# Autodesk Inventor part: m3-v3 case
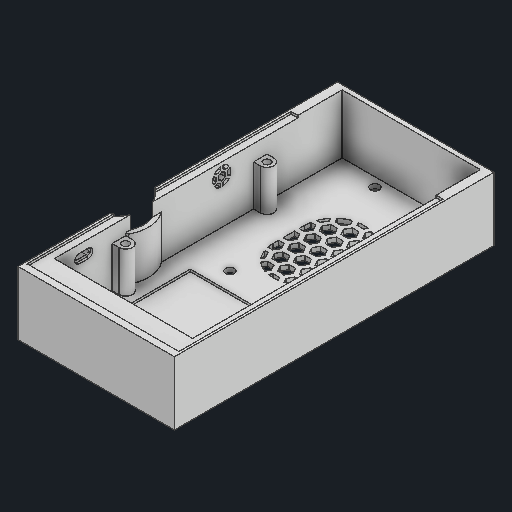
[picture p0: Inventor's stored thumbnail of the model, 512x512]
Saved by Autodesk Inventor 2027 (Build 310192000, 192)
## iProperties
Created: 2026-10
Part Number: m3-v3 case
Material: 일반
Document SubType Name: Modeling
Designer: khw
Density: 1 g/cm^3
Appearance: 기본값
Author: khw
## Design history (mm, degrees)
sketch "스케치1"
  geometry: L1 (0, 0)-(61, 0); L2 (61, 0)-(61, -106); L3 (61, -106)-(0, -106); L4 (0, -106)-(0, 0); L5 (64, 9)-(-3, 9); L6 (-3, 9)-(-3, -107.5); L7 (-3, -107.5)-(64, -107.5); L8 (64, -107.5)-(64, 9); L9 (49, -10)-(35, -10); L10 (35, -10)-(35, -17); L11 (35, -17)-(49, -17); L12 (49, -17)-(49, -10); L13 (58, -28.5)-(3, -28.5); L14 (3, -28.5)-(3, -90.9); L15 (3, -90.9)-(58, -90.9); L16 (58, -90.9)-(58, -28.5); L17 (52, -25)-(9, -25); L18 (9, -25)-(9, -51); L19 (9, -51)-(52, -51); L20 (52, -51)-(52, -25); L21 (18.5, -59)-(42.5, -59); L22 (30.5, -65)-(30.5, -79); L23 (35.119, -80)-(38.006, -80); L24 (31.943, -81.5)-(29.057, -81.5); L25 (33.387, -79)-(31.943, -81.5); L26 (29.057, -81.5)-(27.613, -79); L27 (42.5, -113)-(42.5, -49); L28 (18.5, -113)-(18.5, -49); L29 (18.5, -49)-(18.5, -113); L30 (42.5, -59)-(42.5, -123); L31 (18.5, -123)-(18.5, -59); L32 (18.5, -59)-(18.5, -123); L33 (42.5, -123)-(18.5, -123); L34 (33.675, -82.5)-(35.119, -80); L35 (22.994, -71)-(25.881, -71); L36 (27.613, -72)-(29.057, -69.5); L37 (29.057, -74.5)-(27.613, -72); L38 (31.943, -69.5)-(33.387, -72); L39 (29.057, -76.5)-(31.943, -76.5); L40 (39.449, -68.5)-(38.006, -71); L41 (31.943, -76.5)-(33.387, -79); L42 (29.057, -69.5)-(31.943, -69.5); L43 (25.881, -71)-(27.325, -68.5); L44 (35.119, -71)-(33.675, -68.5); L45 (38.006, -71)-(35.119, -71); L46 (38.006, -80)-(39.449, -82.5); L47 (39.449, -82.5)-(38.006, -85); L48 (38.006, -85)-(35.119, -85); L49 (30.5, -79)-(30.5, -93); L50 (30.5, -86)-(17.5, -86); L51 (25.881, -87)-(27.325, -89.5); L52 (25.881, -92)-(22.994, -92); L53 (22.994, -87)-(25.881, -87); L54 (21.551, -89.5)-(22.994, -87); L55 (22.994, -92)-(21.551, -89.5); L56 (17.5, -93)-(17.5, -79); L57 (17.5, -79)-(17.5, -93); L58 (27.613, -86)-(29.057, -88.5); L59 (30.5, -93)-(30.5, -79); L60 (31.943, -90.5)-(29.057, -90.5); L61 (29.057, -88.5)-(31.943, -88.5); L62 (29.057, -67.5)-(27.613, -65); L63 (35.119, -66)-(38.006, -66); L64 (39.738, -79)-(41.181, -76.5)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; C1 r 1.6 at (58, -28.5); C2 r 1.6 at (3, -28.5); C3 r 1.6 at (3, -90.9); C4 r 1.6 at (58, -90.9); C5 r 2 at (42.5, -59); C6 r 2 at (18.5, -59); C7 r 2 at (18.5, -123); C8 r 2 at (42.5, -123); A1 r 3 centre (58, -28.5) between (58, -25.5) and (58, -31.5); A2 r 3 centre (3, -28.5) between (3, -31.5) and (3, -25.5); A3 r 3 centre (3, -90.9) between (3, -93.9) and (3, -87.9); A4 r 3 centre (58, -90.9) between (58, -93.9) and (58, -87.9); A5 r 13 centre (30.5, -79) between (43.5, -79) and (17.5, -79); A6 r 13 centre (30.5, -79) between (43.5, -79) and (17.5, -79); A7 r 13 centre (30.5, -93) between (17.5, -93) and (43.5, -93); A8 r 13 centre (30.5, -93) between (17.5, -93) and (43.5, -93); A9 r 13 centre (30.5, -93) between (17.5, -93) and (43.5, -93); A10 r 12.5 centre (72.5, -38.5) between (65, -28.5) and (65, -48.5); A11 r 14.5 centre (72.5, -38.5) between (59.802, -31.5) and (65, -50.91); 91 further points; 1 other entity
  constraints: 492 end point, 151 symmetric about line, 26 point on circle, 20 parallel, 19 centre point, 19 coincident, 17 midpoint, 14 perpendicular, 11 horizontal, 10 point on line, 9 tangent, 6 vertical alignment, 4 vertical, 3 equal length, 1 concentric, 1 line through centre, 147 other
  dimensions: "d0" = 61 distance of L2.end L3.end; "d1" = 106 distance of L1.end L2.end; "d2" = 9 distance between parallel lines of L1 L5; "d3" = 1.5 distance between parallel lines of L7 L3; "d4" = 3 distance between parallel lines of L2 L8; "d6" = 13.5 distance from line of L1 point (49, -13.5); "d8" = 7 distance of L11.end L9.start; "d9" = 14 distance of L10.end L11.end; "d11" = 62.4 distance of L15.end L13.start; "d12" = 55 distance of L13.start L13.end; "d13" = 3.2 diameter of C1; "d14" = 6 diameter of A1; "d15" = 3.2 diameter of C2; "d16" = 6 diameter of A2; "d17" = 3.2 diameter of C3; "d18" = 6 diameter of A3; "d19" = 3.2 diameter of C4; "d20" = 6 diameter of A4; "d22" = 26 distance of L17.end L18.end; "d23" = 43 distance of L18.end L19.end; "d24" = 22 distance from line of L8 point (42, -17); "d33" = 24 distance of L21.start L21.end; "d34" = 64 distance of L31.start L21.start; "d35" = 4 diameter of C5; "d36" = 4 diameter of C6; "d37" = 4 diameter of C8; "d38" = 4 diameter of C7; "d39" = 27 distance from line of L21 point (30.5, -86); "d40" = 40 distance of point (30.5, -106) point (30.5, -66); "d41" = 26 distance between parallel lines of L80 L72; "d42" = 2 distance between parallel lines of L24 L201; "d43" = 2 distance from line of point (32.665, -84.75) L204; "d44" = 2 distance between parallel lines of L25 L34; "d45" = 7 distance of L49.start L180.start; "d46" = 2 distance between parallel lines of L46 L73; "d47" = 2 distance from line of point (38.727, -76.75) L64; "d48" = 7 distance of L73.start L65.start; "d51" = 8 distance from line of point (30.5, -51) L21; "d52" = 8 distance between parallel lines of L11 L17; "d53" = 3 distance between parallel lines of L225 L5; "d54" = 6 distance from line of L227 point (30.5, -123); "d55" = 1 distance between parallel lines of L226 L6; "d56" = 10 distance from line of A1.centre L228; "d57" = 20 distance of A10.end A10.start; "d58" = 1 distance from line of L228.start L2; "d59" = 2 distance between parallel lines of L227 L231; "d70" = 2 radial gap between concentric circles of A11 A10; "d77" = 28.5 distance between parallel lines of L1 L13
  node "스케치 - 직사각형 패턴1" dims "d45" = 7, "d49" = 10
  node "스케치 - 직사각형 패턴2" dims "d48" = 7, "d50" = 10
extrude "돌출1" new body sketch "스케치1" distance "d60" = 2; taper "d61" = 0 deg
extrude "돌출2" join sketch "스케치1" distance "d62" = 26; taper "d63" = 0 deg
extrude "돌출3" cut sketch "스케치1" distance "d64" = 1; taper "d65" = 0 deg
extrude "돌출4" join sketch "스케치1" distance "d66" = 18; taper "d67" = 0 deg; dims "d68" = 2, "d69" = 0
extrude "돌출5" join sketch "스케치1" distance "d71" = 19.2; taper "d72" = 0 deg
sketch "스케치2"
  geometry: L1 (-39.449, 75.5)-(-38.006, 78) reference; L2 (-39.738, 86)-(-41.181, 88.5) reference; L3 (-41.181, 88.5)-(-39.738, 86) reference; L4 (-29.057, 88.5)-(-31.943, 88.5) reference; L5 (-31.943, 88.5)-(-29.057, 88.5) reference; L6 (-35.119, 92)-(-38.006, 92) reference; L7 (-44.068, 88.5)-(-41.181, 88.5) reference; L8 (-41.181, 88.5)-(-44.068, 88.5) reference; L9 (-45.511, 86)-(-44.068, 88.5) reference; L10 (-44.068, 88.5)-(-45.511, 86) reference; L11 (-44.068, 83.5)-(-45.511, 86) reference; L12 (-22.994, 92)-(-21.551, 89.5) reference; L13 (-15.489, 79)-(-16.932, 81.5) reference; L14 (-15.489, 86)-(-16.932, 88.5) reference; L15 (-16.932, 88.5)-(-15.489, 86) reference; L16 (-22.994, 80)-(-21.551, 82.5) reference; L17 (-19.819, 81.5)-(-21.262, 79) reference; L18 (-25.881, 80)-(-22.994, 80) reference; L19 (-21.551, 82.5)-(-22.994, 85) reference; L20 (-22.994, 78)-(-25.881, 78) reference; L21 (-16.932, 81.5)-(-19.819, 81.5) reference; L22 (-21.262, 79)-(-19.819, 76.5) reference; L23 (-19.819, 76.5)-(-16.932, 76.5) reference; L24 (-16.932, 76.5)-(-15.489, 79) reference; L25 (-22.994, 85)-(-25.881, 85) reference; L26 (-27.325, 89.5)-(-25.881, 92) reference; L27 (-43.5, 79)-(-43.5, 93) reference; L28 (-19.819, 90.5)-(-21.262, 93) reference; L29 (-16.932, 88.5)-(-19.819, 88.5) reference; L30 (-19.819, 88.5)-(-16.932, 88.5) reference; L31 (-16.932, 83.5)-(-15.489, 86) reference; L32 (-19.819, 83.5)-(-16.932, 83.5) reference; L33 (-16.932, 102.5)-(-15.489, 100) reference; L34 (-35.119, 99)-(-38.006, 99) reference; L35 (-33.675, 96.5)-(-35.119, 99) reference; L36 (-35.119, 101)-(-33.675, 103.5) reference; L37 (-39.449, 103.5)-(-38.006, 101) reference; L38 (-38.006, 106)-(-39.449, 103.5) reference; L39 (-33.387, 107)-(-31.943, 104.5) reference; L40 (-25.881, 78)-(-27.325, 75.5) reference; L41 (-35.119, 78)-(-33.675, 75.5) reference; L42 (-38.006, 78)-(-35.119, 78) reference; L43 (-27.613, 79)-(-29.057, 76.5) reference; L44 (-44.068, 76.5)-(-45.511, 79) reference; L45 (-41.181, 76.5)-(-44.068, 76.5) reference; L46 (-35.119, 73)-(-38.006, 73) reference; L47 (-27.325, 75.5)-(-25.881, 73) reference; L48 (-39.738, 93)-(-41.181, 95.5) reference; L49 (-41.181, 97.5)-(-39.738, 100) reference; L50 (-44.068, 95.5)-(-45.511, 93) reference; L51 (-41.181, 95.5)-(-44.068, 95.5) reference; L52 (-39.738, 100)-(-41.181, 102.5) reference; L53 (-44.068, 97.5)-(-41.181, 97.5) reference; L54 (-41.181, 102.5)-(-44.068, 102.5) reference; L55 (-45.511, 100)-(-44.068, 97.5) reference; L56 (-44.068, 102.5)-(-45.511, 100) reference; L57 (-33.387, 100)-(-31.943, 97.5) reference; L58 (-31.943, 97.5)-(-29.057, 97.5) reference; L59 (-35.119, 94)-(-33.675, 96.5) reference; L60 (-31.943, 95.5)-(-33.387, 93) reference; L61 (-29.057, 95.5)-(-31.943, 95.5) reference; L62 (-38.006, 101)-(-35.119, 101) reference; L63 (-29.057, 102.5)-(-31.943, 102.5) reference; L64 (-35.119, 106)-(-38.006, 106) reference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; C1 r 2 at (-18.5, 123) reference; C2 r 1.6 at (-58, 90.9) reference; C3 r 2 at (-18.5, 59) reference; C4 r 2 at (-42.5, 59) reference; C5 r 1.6 at (-3, 90.9) reference; C6 r 2 at (-42.5, 123) reference; C7 r 1.6 at (-3, 28.5) reference; C8 r 1.6 at (-58, 28.5) reference; A1 r 13 centre (-30.5, 93) between (-17.5, 93) and (-43.5, 93) reference; A2 r 13 centre (-30.5, 93) between (-17.5, 93) and (-43.5, 93) reference; A3 r 13 centre (-30.5, 93) between (-17.5, 93) and (-43.5, 93) reference; A4 r 3 centre (-58, 90.9) between (-58, 87.9) and (-58, 93.9) reference; A5 r 13 centre (-30.5, 79) between (-43.5, 79) and (-17.5, 79) reference; A6 r 13 centre (-30.5, 79) between (-43.5, 79) and (-17.5, 79) reference; A7 r 12.5 centre (-72.5, 38.5) between (-65, 28.5) and (-65, 48.5) reference; A8 r 14.5 centre (-72.5, 38.5) between (-59.802, 31.5) and (-65, 50.91) reference; 85 further points; 3 other entities
  constraints: 3 vertical alignment, 7 other
extrude "돌출6" cut sketch "스케치2" distance "d73" = 1; taper "d74" = 0 deg
sketch "스케치3"
  geometry: L1 (98.9, 20)-(102.1, 20) reference; L2 (36.5, 20)-(39.7, 20) reference; L3 (55.1, 23.232)-(56.6, 22.366); L4 (56.6, 22.366)-(56.6, 20.634); L5 (56.6, 20.634)-(55.1, 19.768); L6 (55.1, 19.768)-(53.6, 20.634); L7 (53.6, 20.634)-(53.6, 22.366); L8 (53.6, 22.366)-(55.1, 23.232); L9 (59.1, 23.232)-(60.6, 22.366); L10 (60.6, 22.366)-(60.6, 20.634); L11 (60.6, 20.634)-(59.1, 19.768); L12 (59.1, 19.768)-(57.6, 20.634); L13 (57.6, 20.634)-(57.6, 22.366); L14 (57.6, 22.366)-(59.1, 23.232); L15 (55.1, 17.5)-(55.1, 25.5); L16 (55.6, 25.83)-(57.1, 26.696); L17 (57.1, 26.696)-(58.6, 25.83); L18 (58.6, 25.83)-(58.6, 24.098); L19 (57.1, 23.232)-(55.6, 24.098); L20 (58.6, 24.098)-(57.1, 23.232); L21 (55.6, 24.098)-(55.6, 25.83); L22 (51.6, 24.098)-(51.6, 25.83); L23 (51.6, 25.83)-(53.1, 26.696); L24 (53.1, 26.696)-(54.6, 25.83); L25 (54.6, 24.098)-(53.1, 23.232); L26 (54.6, 25.83)-(54.6, 24.098); L27 (53.1, 23.232)-(51.6, 24.098); L28 (51.1, 19.768)-(49.6, 20.634); L29 (49.6, 20.634)-(49.6, 22.366); L30 (49.6, 22.366)-(51.1, 23.232); L31 (52.6, 22.366)-(52.6, 20.634); L32 (51.1, 23.232)-(52.6, 22.366); L33 (52.6, 20.634)-(51.1, 19.768); L34 (54.6, 17.17)-(53.1, 16.304); L35 (53.1, 16.304)-(51.6, 17.17); L36 (51.6, 17.17)-(51.6, 18.902); L37 (53.1, 19.768)-(54.6, 18.902); L38 (51.6, 18.902)-(53.1, 19.768); L39 (54.6, 18.902)-(54.6, 17.17); L40 (58.6, 18.902)-(58.6, 17.17); L41 (58.6, 17.17)-(57.1, 16.304); L42 (57.1, 16.304)-(55.6, 17.17); L43 (55.6, 18.902)-(57.1, 19.768); L44 (55.6, 17.17)-(55.6, 18.902); L45 (57.1, 19.768)-(58.6, 18.902); L46 (114, 21.5)-(118, 21.5); L47 (114, 20.5)-(118, 20.5); L48 (118, 22.5)-(114, 22.5); C1 r 1 at (116, 21.5); A1 r 4 centre (55.1, 21.5) between (59.1, 21.5) and (55.1, 17.5); A2 r 1 centre (114, 21.5) between (114, 22.5) and (114, 20.5); A3 r 1 centre (118, 21.5) between (118, 20.5) and (118, 22.5); 19 further points
  constraints: 94 end point, 9 point on circle, 5 tangent, 4 centre point, 4 midpoint, 2 coincident, 2 horizontal alignment, 2 parallel, 1 horizontal, 1 vertical, 99 other
  dimensions: "d75" = 1.5 distance from line of L1 C1.centre; "d76" = 15.5 horizontal distance of C1.centre point (100.5, 20); "d78" = 8 diameter of A1; "d79" = 2 diameter of C1; "d80" = 17 horizontal distance of A1.centre point (38.1, 20); "d81" = 8 distance of L15.start L15.end; "d82" = 1 distance between parallel lines of L13 L4; "d85" = 360 deg dimension on A1.centre L9.start (derived); "d87" = 6 distance of point (119, 21.5) point (113, 21.5)
extrude "돌출7" cut sketch "스케치3" stored distance "d88" = 8 (derived); taper "d89" = 0 deg
sketch "스케치4"
  geometry: L1 (-10.5, 20.5)-(-14.5, 20.5) reference; L2 (-14.5, 18.5)-(-10.5, 18.5) reference; L3 (3, 26)-(3, -2) reference; L4 (-37.5, -2)-(3, -2) reference; L5 (-37.5, -2)-(-37.5, 26) reference; L6 (3, 26)-(-37.5, 26) reference; L7 (-10.5, 19.5)-(-14.5, 19.5); L8 (-10.5, 21.5)-(-14.5, 21.5); L9 (-14.5, 17.5)-(-10.5, 17.5); A1 r 1 centre (-10.5, 19.5) between (-10.5, 18.5) and (-10.5, 20.5) reference; A2 r 1 centre (-14.5, 19.5) between (-14.5, 20.5) and (-14.5, 18.5) reference; A3 r 2 centre (-10.5, 19.5) between (-10.5, 17.5) and (-10.5, 21.5); A4 r 2 centre (-14.5, 19.5) between (-14.5, 21.5) and (-14.5, 17.5); 2 further points
  constraints: 8 end point, 4 point on circle, 4 tangent, 2 centre point, 1 horizontal, 1 midpoint, 1 parallel
  dimensions: "d90" = 4 diameter of A4
extrude "돌출8" cut sketch "스케치4" distance "d91" = 1; taper "d92" = 0 deg
node "솔리드1"
node "스케치 - 원형 패턴1" dims "d85" = 360 deg (derived)
node "투영된 루프1"
